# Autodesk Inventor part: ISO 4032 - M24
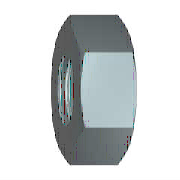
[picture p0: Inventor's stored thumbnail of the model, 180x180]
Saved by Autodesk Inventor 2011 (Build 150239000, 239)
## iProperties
IsCustomPart: 0
Created: 2009-02
Part Number: ISO 4032 - M24
Material: Stainless Steel, 440C
Description: Hexagon nuts, style 1 - Product grades A and B
Document SubType Name: Modeling
Standard: ISO 4032
Designer: V.de Jong
Standard Revision: Third edition 1999-08-15
Standards Organization: ISO
Language: en-US
Size Designation: M24
Categories: <MemberInstance><Categories><Category DisplayName="Fasteners" InternalName="e4da775c-781d-43d5-af7c-5136215cf5a6" Mnemonic="FSTN"><Category DisplayName="Nuts" I
Density: 7.75 g/cm^3
Mass: 126.901 g
Surface Area: 53.1027 cm^2
Volume: 16.3744 cm^3
Author: V.de Jong
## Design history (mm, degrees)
body "Solid1"
workaxis "Work Axis1"
workplane "Work Plane1"
sketch "Sketch1"
  geometry: L1 (-20.785, 0)-(-10.392, 18); L2 (-10.392, 18)-(10.392, 18); L3 (10.392, 18)-(20.785, 0); L4 (20.785, 0)-(10.392, -18); L5 (10.392, -18)-(-10.392, -18); L6 (-10.392, -18)-(-20.785, 0); 2 further points
  constraints: 12 end point, 1 coincident, 1 horizontal, 11 other
  dimensions: "d0" = 41.56922 distance of L3.end L1.start (= 1.1547 x SW)
extrude "Body" new body sketch "Sketch1" distance "d1" = 21.5 (= KOH); taper "d2" = 0 deg
revolve "Chamfer1" stored, may be unused: angle "d7" = 90 deg
sketch "Sketch3"
  geometry: 4 further points
  constraints: 1 coincident, 1 other
hole "Thread" sketch "Sketch3" diameter "d25" = 20.752; stored, may be unused: countersink angle "d29" = 82 deg, drill point angle "d31" = 118 deg; dims "d26" = 6, "d27" = 4, "d28" = 2, "d30" = 8
chamfer "Chamfer2" distance "d8" = 1.6238 (= -0.5 x GD1 + 0.5 x NND); stored, may be unused: angle "d9" = 30 deg, second distance "d40" = 1.6238 (= -0.5 x GD1 + 0.5 x NND)
chamfer "Chamfer3" distance "d10" = 1.6238 (= -0.5 x GD1 + 0.5 x NND); stored, may be unused: angle "d11" = 30 deg, second distance "d41" = 1.6238 (= -0.5 x GD1 + 0.5 x NND)
sketch "Sketch2"
  geometry: L1 (0, 10.392)-(0, 20.785) reference; L2 (0, 20.785)-(21.5, 20.785) reference; L3 (21.5, 10.392)-(21.5, 20.785) reference; L4 (-4.3, 0)-(25.8, 0) reference; L5 (2.387, 20.785)-(0, 16.65); L6 (19.113, 20.785)-(21.5, 16.65)
  constraints: 4 end point, 4 point on line
  dimensions: "d3" = 30 deg angle of L1 L5 (= ANG1); "d4" = 30 deg angle of L3 L6 (= ANG2); "d5" = 33.3 diameter of L5.end L4 (= SW0); "d6" = 33.3 diameter of L6.end L4 (= SW01)
other parameters: "ANG1" = 30 deg [user parameter; used in 1 equation term], "ANG2" = 30 deg [user parameter; used in 1 equation term], "NND" = 24 [user parameter; used in 4 equation terms], "KOH" = 21.5 [user parameter; used in 1 equation term], "SW" = 36 [user parameter; used in 2 equation terms], "SW0" = 33.3 [user parameter; used in 2 equation terms], "SW01" = 33.3 (= SW0) [user parameter; used in 1 equation term], "GD1" = 20.7524 (computed from THREADDIA, PTC, TOA) [user parameter; used in 4 equation terms], "d13" = 0, "d14" = 0, "d39" = 0, "d42" = 0, "GUL" = 1.6238 (= 0.541266 x PTC) [user parameter], "TPU" = 3.33333 (computed from PTC) [user parameter], "THREADDIA" = 24 [user parameter; used in 1 equation term], "TOA" = 30 deg [user parameter; used in 1 equation term], "PTC" = 3 [user parameter; used in 4 equation terms], "E0" = 41.58 (= 1.155 x SW) [user parameter], "GAL" = 1.6238 (= 0.541266 x PTC) [user parameter]
